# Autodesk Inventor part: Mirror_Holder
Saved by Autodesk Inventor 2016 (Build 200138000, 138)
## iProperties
Created: 2015-11
Part Number: Mirror_Holder
Material: Generic
Document SubType Name: Modeling
Designer: John
Density: 1 g/cm^3
Appearance: Default
Author: John
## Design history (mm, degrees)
feature "SOLID1"
body "Solid1"
